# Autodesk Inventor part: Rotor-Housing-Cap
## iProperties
Shininess: 64.0
Length Units: 11269
Angle Units: 11279
Time Units: 11290
Mass Units: 11283
Length Display Precision: 3
Angle Display Precision: 2
Compacted: True
Part Number: Rotor-Housing-Cap
Document SubType Name: Modeling
Created: 2004-01
Designer: Administrator
Manufacturer: Standard
Standards Organization: Custom
Density: 1 g/cm^3
Density: 0.0
Volumn: 0.0
Area: 0.0
PropertySet Name: Model Information
Control State: 0
Master: False
Checked Out: False
Author: Administrator
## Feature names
1. Extrusion1
